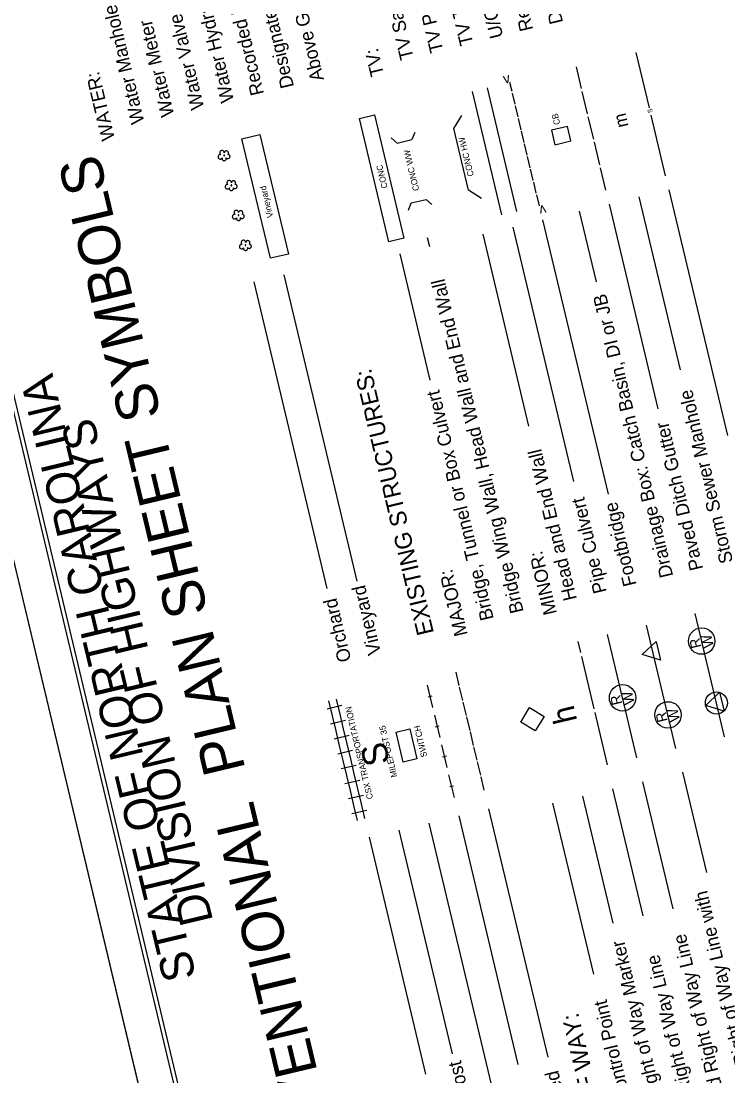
# Model space of a CAD drawing. Extents: x 1734738 to 1742883, y 698103 to 703125.
# Drawn here: x 1737661 to 1738581, y 700083 to 701455 of the extents above; entities that cross this region are included whole.
import ezdxf

# ---------------------------------------------------------------- set-up
doc = ezdxf.new("R2010")
doc.units = 0
for name, color, linetype in [('Exist Map Preparation Border Sheet 1 CELL', 7, 'Continuous'), ('Exist Road Primary Interstate Shield CELL', 7, 'Continuous'), ('Exist Road Primary US Structure Standard Bridge Number Label', 7, 'Continuous'), ('Exist Road Secondary Structure Pipe Number Label', 7, 'Continuous'), ('Exist Road Secondary Type 41 SR Number Label', 7, 'Continuous'), ('Level 57', 7, 'Continuous')]:
    doc.layers.add(name, color=color, linetype=linetype)

msp = doc.modelspace()

# ---------------------------------------------------------------- linework, layer by layer
at = {"layer": 'Exist Road Primary Interstate Shield CELL'}
for p, q in [((1738478.8, 701342.3), (1738461.7, 701414.3)), ((1738390.6, 701367.5), (1738383.9, 701395.7)), ((1738287, 701203), (1738248.8, 701363.5)), ((1738306.5, 701207.6), (1738268.2, 701368.1)), ((1738300.2, 701363.4), (1738297.4, 701375.1)), ((1738398.5, 701334.4), (1738391.5, 701363.6)), ((1738304.2, 701346.9), (1738300.7, 701361.5)), ((1738308.1, 701330.4), (1738304.6, 701344.9)), ((1738224.3, 701315.3), (1738234.8, 701332.3)), ((1738312, 701313.8), (1738308.6, 701328.4)), ((1738406.4, 701301.3), (1738399.4, 701330.5)), ((1738499.9, 701253.7), (1738481.2, 701332.6)), ((1738173.7, 701310.3), (1738170, 701301)), ((1738243.4, 701235), (1738224.3, 701315.3)), ((1738316, 701297.3), (1738312.5, 701311.9)), ((1738143.1, 701303.1), (1738150.5, 701296.4)), ((1738150.5, 701296.4), (1738170, 701301)), ((1738319.9, 701280.7), (1738316.4, 701295.3)), ((1738414.2, 701268.3), (1738407.3, 701297.5)), ((1738323.9, 701264.2), (1738320.4, 701278.8)), ((1738327.8, 701247.7), (1738324.3, 701262.3)), ((1738422.1, 701235.2), (1738415.2, 701264.4)), ((1738331.7, 701231.1), (1738328.3, 701245.7)), ((1738260.5, 701224.5), (1738243.4, 701235)), ((1738335.7, 701214.6), (1738332.2, 701229.2)), ((1738465.3, 701226.4), (1738519, 701001.3)), ((1738504.3, 701235.7), (1738580.4, 700916.2)), ((1738165.4, 701209.3), (1738169.1, 701218.6)), ((1738169.1, 701218.6), (1738188.5, 701223.2)), ((1738196, 701216.6), (1738188.5, 701223.2)), ((1738426.4, 701217.1), (1738489.9, 700950.7)), ((1738387.5, 701207.8), (1738409.4, 701116)), ((1738301.1, 701187.2), (1738380, 700856.1)), ((1738340, 701196.5), (1738425.1, 700839.6)), ((1738193, 701161.5), (1738190.2, 701173.1)), ((1738262.2, 701178), (1738321.7, 700928.3)), ((1738154.1, 701152.2), (1738193.2, 700987.9)), ((1737964.4, 701115.9), (1738059.4, 700717.1)), ((1738003.3, 701125.1), (1738098.3, 700726.4)), ((1738576.6, 700524), (1738538.4, 700684.5)), ((1738513.4, 700508.9), (1738475.1, 700669.5)), ((1738462.6, 700496.8), (1738424.3, 700657.3)), ((1738389.8, 700633.7), (1738386.3, 700648.3)), ((1738407.2, 700560.7), (1738390.9, 700628.8)), ((1738483.5, 700634.3), (1738483.5, 700634.3)), ((1738231.5, 700590.8), (1738227.4, 700608.3)), ((1738197.3, 700562.1), (1738190.3, 700591.3)), ((1738236.2, 700571.4), (1738232, 700588.9)), ((1738066.6, 700551.5), (1738062, 700571)), ((1738076.4, 700553.8), (1738071.7, 700573.3)), ((1738191.4, 700576.1), (1738196.2, 700577.3)), ((1738240.8, 700551.9), (1738236.6, 700569.4)), ((1738566.1, 700568.2), (1738566.1, 700568.2)), ((1738078.9, 700564.7), (1738059.5, 700560.1)), ((1738081, 700534.4), (1738076.4, 700553.8)), ((1738424.5, 700487.8), (1738408.3, 700555.9)), ((1738083.5, 700545.3), (1738064.1, 700540.6)), ((1738071.3, 700532.1), (1738066.6, 700551.5)), ((1738206.5, 700523.2), (1738199.6, 700552.4)), ((1738245.5, 700532.5), (1738241.3, 700550)), ((1738088.2, 700525.8), (1738068.7, 700521.2)), ((1738075.9, 700512.6), (1738071.3, 700532.1)), ((1738085.6, 700514.9), (1738081, 700534.4)), ((1738200.6, 700537.2), (1738205.5, 700538.4)), ((1738250.1, 700513), (1738245.9, 700530.5)), ((1738080.5, 700493.2), (1738075.9, 700512.6)), ((1738090.3, 700495.5), (1738085.6, 700514.9)), ((1738215.8, 700484.3), (1738208.9, 700513.5)), ((1738092.8, 700506.4), (1738073.4, 700501.7)), ((1738209.9, 700498.3), (1738214.8, 700499.4)), ((1738254.7, 700493.6), (1738250.6, 700511.1)), ((1738097.5, 700486.9), (1738078, 700482.3)), ((1738085.2, 700473.7), (1738080.5, 700493.2)), ((1738094.9, 700476), (1738090.3, 700495.5)), ((1738259.4, 700474.1), (1738255.2, 700491.6)), ((1738089.8, 700454.2), (1738085.2, 700473.7)), ((1738099.5, 700456.6), (1738094.9, 700476)), ((1738225.1, 700445.4), (1738218.1, 700474.6)), ((1738264, 700454.6), (1738259.8, 700472.2)), ((1738522, 700478), (1738553.1, 700347.5)), ((1738102.1, 700467.5), (1738082.6, 700462.8)), ((1738219.2, 700459.4), (1738224, 700460.5)), ((1738469.8, 700465.6), (1738509.2, 700300.3)), ((1738106.7, 700448), (1738087.3, 700443.4)), ((1738094.5, 700434.8), (1738089.8, 700454.2)), ((1738104.2, 700437.1), (1738099.5, 700456.6)), ((1738391.9, 700447), (1738431.3, 700281.8)), ((1738430.9, 700456.3), (1738470.2, 700291.1)), ((1738099.1, 700415.3), (1738094.5, 700434.8)), ((1738108.8, 700417.7), (1738104.2, 700437.1)), ((1738269.7, 700430.5), (1738346.8, 700107.3)), ((1738269.7, 700430.5), (1738346.8, 700107.3)), ((1738353, 700437.8), (1738406, 700215.6)), ((1738111.4, 700428.5), (1738091.9, 700423.9)), ((1738230.8, 700421.3), (1738307.9, 700098)), ((1738153, 700402.7), (1738222.4, 700111.8)), ((1738191.9, 700412), (1738291.6, 699993.9)), ((1738114.1, 700393.4), (1738187.6, 700085.2))]:
    msp.add_line(p, q, dxfattribs=at)
for points in [[(1737411.4, 701976.4), (1738106.9, 699058.2), (1740147.7, 699544.6), (1739452.2, 702462.8)], [(1738376.7, 701299.3), (1738372.2, 701318), (1738351.5, 701313), (1738356, 701294.3)], [(1738493.4, 700623.8), (1738469.5, 700631), (1738487.6, 700648.2)], [(1738576, 700557.7), (1738552.1, 700564.8), (1738570.2, 700582)], [(1738158.7, 700491.2), (1738149.4, 700530.1), (1738167.2, 700534.4), (1738176.4, 700495.5)]]:
    msp.add_lwpolyline(points, close=True, dxfattribs=at)
for points in [[(1738140, 701168), (1738101.8, 701328.5), (1738121.2, 701333.1), (1738159.5, 701172.6), (1738140, 701168)], [(1737985.9, 701146.5), (1737948.8, 701302.1), (1737972.1, 701307.7), (1738009.2, 701152), (1737985.9, 701146.5)], [(1737921.4, 701281.3), (1737920.7, 701281.4), (1737920.1, 701281.4), (1737919.5, 701281.1), (1737919, 701280.9), (1737918.6, 701280.5), (1737918.2, 701280.1), (1737917.9, 701279.5), (1737917.7, 701279), (1737917.7, 701278.2), (1737917.8, 701277.7), (1737918, 701277.2), (1737918.4, 701276.6), (1737918.8, 701276.2), (1737919.3, 701275.8), (1737919.9, 701275.7), (1737920.5, 701275.6), (1737921.1, 701275.6), (1737921.6, 701275.8), (1737922.2, 701276), (1737922.6, 701276.4), (1737923.1, 701277), (1737922.9, 701276.4), (1737923, 701275.8), (1737923.1, 701275.2), (1737923.4, 701274.8), (1737923.7, 701274.3), (1737924.2, 701273.9), (1737924.7, 701273.6), (1737925.3, 701273.5), (1737925.8, 701273.5), (1737926.5, 701273.6), (1737927, 701273.8), (1737927.4, 701274.1), (1737927.8, 701274.6), (1737928.1, 701275), (1737928.3, 701275.5), (1737928.4, 701276.2), (1737928.4, 701276.7), (1737928.3, 701277.3), (1737928.6, 701276.8), (1737929.1, 701276.4), (1737929.6, 701276.2), (1737930.2, 701276.2), (1737930.8, 701276.1), (1737931.3, 701276.2), (1737931.9, 701276.5), (1737932.3, 701276.9), (1737932.7, 701277.3), (1737933, 701277.8), (1737933.2, 701278.3), (1737933.3, 701278.9), (1737933.1, 701279.4), (1737933, 701280), (1737932.8, 701280.5), (1737932.3, 701280.9), (1737931.8, 701281.3), (1737930.9, 701281.6)], [(1737930.9, 701281.6), (1737931.3, 701282.9), (1737931.3, 701283.5), (1737931.3, 701284.1), (1737931, 701284.7), (1737930.7, 701285.1), (1737930.3, 701285.6), (1737929.8, 701286), (1737929.3, 701286.1), (1737928.7, 701286.2), (1737928.1, 701286.3), (1737927.5, 701286), (1737927, 701285.8), (1737926.5, 701285.3), (1737926.2, 701284.9), (1737926, 701284.3), (1737925.8, 701283.7), (1737925.8, 701284.3), (1737925.6, 701285), (1737925.3, 701285.4), (1737924.9, 701285.9), (1737924.5, 701286.3), (1737923.9, 701286.6), (1737923.2, 701286.8), (1737922.6, 701286.7), (1737922, 701286.7), (1737921.5, 701286.4), (1737920.9, 701286.1), (1737920.5, 701285.6), (1737920.2, 701285), (1737920, 701284.4), (1737919.9, 701283.8), (1737920, 701283.2), (1737920.1, 701282.6), (1737920.5, 701282.1), (1737920.9, 701281.7), (1737921.4, 701281.3)], [(1737925.2, 701280.4), (1737925.2, 701280.1), (1737925.4, 701280), (1737925.5, 701279.8), (1737925.8, 701279.9), (1737926, 701279.9), (1737926.2, 701280.2), (1737926.1, 701280.4), (1737926, 701280.6), (1737925.8, 701280.8), (1737925.5, 701280.8), (1737925.3, 701280.7), (1737925.2, 701280.4)], [(1737930.6, 701242.4), (1737930, 701242.5), (1737929.4, 701242.5), (1737928.8, 701242.2), (1737928.3, 701242), (1737927.8, 701241.6), (1737927.4, 701241.2), (1737927.2, 701240.6), (1737927, 701240.1), (1737926.9, 701239.3), (1737927.1, 701238.8), (1737927.3, 701238.3), (1737927.6, 701237.7), (1737928, 701237.3), (1737928.5, 701236.9), (1737929.2, 701236.8), (1737929.7, 701236.7), (1737930.3, 701236.7), (1737930.9, 701236.9), (1737931.5, 701237.1), (1737931.9, 701237.5), (1737932.4, 701238.1), (1737932.2, 701237.5), (1737932.3, 701236.9), (1737932.4, 701236.3), (1737932.7, 701235.9), (1737933, 701235.4), (1737933.5, 701235), (1737934, 701234.7), (1737934.6, 701234.6), (1737935.1, 701234.6), (1737935.8, 701234.6), (1737936.2, 701234.9), (1737936.7, 701235.2), (1737937.1, 701235.7), (1737937.4, 701236.1), (1737937.6, 701236.6), (1737937.7, 701237.3), (1737937.7, 701237.8), (1737937.6, 701238.4), (1737937.9, 701237.9), (1737938.4, 701237.5), (1737938.8, 701237.3), (1737939.5, 701237.3), (1737940.1, 701237.2), (1737940.6, 701237.3), (1737941.1, 701237.6), (1737941.6, 701238), (1737942, 701238.4), (1737942.3, 701238.9), (1737942.4, 701239.4), (1737942.5, 701240), (1737942.4, 701240.5), (1737942.2, 701241.1), (1737942, 701241.6), (1737941.5, 701242), (1737941.1, 701242.4), (1737940.1, 701242.7)], [(1737940.1, 701242.7), (1737940.5, 701244), (1737940.6, 701244.6), (1737940.5, 701245.2), (1737940.3, 701245.8), (1737940, 701246.2), (1737939.6, 701246.7), (1737939.1, 701247), (1737938.5, 701247.2), (1737938, 701247.3), (1737937.4, 701247.4), (1737936.8, 701247.1), (1737936.2, 701246.9), (1737935.8, 701246.4), (1737935.4, 701246), (1737935.3, 701245.4), (1737935.1, 701244.8), (1737935.1, 701245.4), (1737934.9, 701246.1), (1737934.6, 701246.5), (1737934.2, 701247), (1737933.8, 701247.4), (1737933.2, 701247.7), (1737932.5, 701247.8), (1737931.9, 701247.8), (1737931.3, 701247.8), (1737930.7, 701247.5), (1737930.2, 701247.2), (1737929.8, 701246.7), (1737929.4, 701246.1), (1737929.3, 701245.5), (1737929.2, 701244.9), (1737929.3, 701244.3), (1737929.4, 701243.7), (1737929.7, 701243.2), (1737930.1, 701242.8), (1737930.6, 701242.4)], [(1737934.4, 701241.5), (1737934.5, 701241.2), (1737934.7, 701241.1), (1737934.8, 701240.9), (1737935.1, 701241), (1737935.3, 701241), (1737935.4, 701241.2), (1737935.4, 701241.5), (1737935.3, 701241.7), (1737935.1, 701241.9), (1737934.8, 701241.9), (1737934.6, 701241.8), (1737934.4, 701241.5)], [(1737939.9, 701203.5), (1737939.3, 701203.6), (1737938.7, 701203.6), (1737938.1, 701203.3), (1737937.5, 701203.1), (1737937.1, 701202.7), (1737936.7, 701202.3), (1737936.4, 701201.7), (1737936.3, 701201.1), (1737936.2, 701200.4), (1737936.3, 701199.9), (1737936.6, 701199.4), (1737936.9, 701198.8), (1737937.3, 701198.4), (1737937.8, 701198), (1737938.5, 701197.9), (1737939, 701197.8), (1737939.6, 701197.8), (1737940.2, 701198), (1737940.8, 701198.2), (1737941.2, 701198.6), (1737941.7, 701199.1), (1737941.5, 701198.6), (1737941.5, 701198), (1737941.7, 701197.4), (1737942, 701197), (1737942.3, 701196.5), (1737942.8, 701196.1), (1737943.3, 701195.8), (1737943.8, 701195.6), (1737944.3, 701195.7), (1737945, 701195.7), (1737945.5, 701195.9), (1737946, 701196.3), (1737946.3, 701196.8), (1737946.7, 701197.1), (1737946.8, 701197.7), (1737947, 701198.4), (1737947, 701198.9), (1737946.8, 701199.4), (1737947.1, 701199), (1737947.7, 701198.6), (1737948.1, 701198.4), (1737948.7, 701198.4), (1737949.4, 701198.3), (1737949.9, 701198.4), (1737950.4, 701198.7), (1737950.8, 701199.1), (1737951.2, 701199.5), (1737951.5, 701200), (1737951.7, 701200.5), (1737951.8, 701201), (1737951.7, 701201.6), (1737951.5, 701202.2), (1737951.3, 701202.7), (1737950.8, 701203.1), (1737950.4, 701203.5), (1737949.4, 701203.8)], [(1737949.4, 701203.8), (1737949.8, 701205.1), (1737949.9, 701205.7), (1737949.8, 701206.3), (1737949.6, 701206.9), (1737949.3, 701207.3), (1737948.9, 701207.7), (1737948.4, 701208.1), (1737947.8, 701208.3), (1737947.3, 701208.4), (1737946.6, 701208.4), (1737946.1, 701208.2), (1737945.5, 701208), (1737945, 701207.4), (1737944.7, 701207.1), (1737944.5, 701206.5), (1737944.4, 701205.9), (1737944.3, 701206.5), (1737944.2, 701207.1), (1737943.9, 701207.6), (1737943.4, 701208.1), (1737943, 701208.5), (1737942.5, 701208.8), (1737941.8, 701208.9), (1737941.2, 701208.9), (1737940.6, 701208.9), (1737940, 701208.6), (1737939.5, 701208.3), (1737939.1, 701207.8), (1737938.7, 701207.2), (1737938.5, 701206.6), (1737938.5, 701206), (1737938.5, 701205.4), (1737938.7, 701204.8), (1737939, 701204.3), (1737939.4, 701203.8), (1737939.9, 701203.5)], [(1737943.7, 701202.6), (1737943.8, 701202.3), (1737943.9, 701202.1), (1737944.1, 701202), (1737944.4, 701202), (1737944.6, 701202.1), (1737944.7, 701202.3), (1737944.6, 701202.6), (1737944.6, 701202.8), (1737944.4, 701203), (1737944, 701203), (1737943.9, 701202.9), (1737943.7, 701202.6)], [(1737949.2, 701164.5), (1737948.5, 701164.7), (1737947.9, 701164.7), (1737947.4, 701164.4), (1737946.8, 701164.2), (1737946.4, 701163.8), (1737946, 701163.4), (1737945.7, 701162.8), (1737945.5, 701162.2), (1737945.5, 701161.5), (1737945.6, 701161), (1737945.8, 701160.5), (1737946.2, 701159.9), (1737946.6, 701159.5), (1737947.1, 701159.1), (1737947.7, 701159), (1737948.3, 701158.9), (1737948.9, 701158.9), (1737949.5, 701159.1), (1737950, 701159.3), (1737950.4, 701159.7), (1737950.9, 701160.2), (1737950.8, 701159.7), (1737950.8, 701159.1), (1737950.9, 701158.5), (1737951.3, 701158), (1737951.6, 701157.6), (1737952.1, 701157.2), (1737952.6, 701156.9), (1737953.1, 701156.7), (1737953.6, 701156.8), (1737954.3, 701156.8), (1737954.8, 701157), (1737955.2, 701157.3), (1737955.6, 701157.9), (1737955.9, 701158.2), (1737956.1, 701158.8), (1737956.3, 701159.4), (1737956.2, 701160), (1737956.1, 701160.5), (1737956.4, 701160.1), (1737956.9, 701159.7), (1737957.4, 701159.5), (1737958, 701159.4), (1737958.6, 701159.4), (1737959.1, 701159.5), (1737959.7, 701159.7), (1737960.1, 701160.2), (1737960.5, 701160.6), (1737960.8, 701161), (1737961, 701161.6), (1737961.1, 701162.1), (1737960.9, 701162.7), (1737960.8, 701163.3), (1737960.6, 701163.8), (1737960.1, 701164.2), (1737959.7, 701164.6), (1737958.7, 701164.9)], [(1737958.7, 701164.9), (1737959.1, 701166.2), (1737959.1, 701166.8), (1737959.1, 701167.4), (1737958.9, 701168), (1737958.5, 701168.4), (1737958.1, 701168.8), (1737957.6, 701169.2), (1737957.1, 701169.4), (1737956.5, 701169.5), (1737955.9, 701169.5), (1737955.4, 701169.3), (1737954.8, 701169.1), (1737954.3, 701168.5), (1737954, 701168.2), (1737953.8, 701167.6), (1737953.7, 701166.9), (1737953.6, 701167.6), (1737953.5, 701168.2), (1737953.1, 701168.7), (1737952.7, 701169.2), (1737952.3, 701169.6), (1737951.7, 701169.9), (1737951.1, 701170), (1737950.5, 701170), (1737949.9, 701169.9), (1737949.3, 701169.7), (1737948.8, 701169.4), (1737948.4, 701168.9), (1737948, 701168.3), (1737947.8, 701167.7), (1737947.8, 701167.1), (1737947.8, 701166.5), (1737947.9, 701165.9), (1737948.3, 701165.4), (1737948.7, 701164.9), (1737949.2, 701164.5)], [(1737953, 701163.7), (1737953.1, 701163.4), (1737953.2, 701163.2), (1737953.3, 701163.1), (1737953.6, 701163.1), (1737953.8, 701163.2), (1737954, 701163.4), (1737953.9, 701163.7), (1737953.9, 701163.9), (1737953.6, 701164.1), (1737953.3, 701164.1), (1737953.1, 701163.9), (1737953, 701163.7)]]:
    msp.add_lwpolyline(points, dxfattribs=at)
for centre, radius in [((1738546.9, 700648.7), 17.2), ((1738444, 700574.9), 17.2), ((1738566.1, 700568.2), 14.4), ((1738503, 700552.6), 17.2)]:
    msp.add_circle(centre, radius, dxfattribs=at)
at = {"layer": 'Exist Road Primary US Structure Standard Bridge Number Label'}
msp.add_line((1737354.8, 701997.9), (1738135.7, 698721.7), dxfattribs=at)
at = {"layer": 'Exist Road Secondary Structure Pipe Number Label'}
msp.add_lwpolyline([(1740226.1, 699246.6), (1739453.3, 702488.8), (1737400.6, 701999.6), (1738173.4, 698757.4)], close=True, dxfattribs=at)
at = {"layer": 'Exist Road Secondary Type 41 SR Number Label'}
msp.add_lwpolyline([(1740275.8, 699231.7), (1739494.9, 702508), (1737354.8, 701997.9), (1738135.7, 698721.7)], close=True, dxfattribs=at)
at = {"layer": 'Level 57'}
msp.add_lwpolyline([(1738330.2, 700531.7), (1738311.4, 700543.3), (1738323, 700562.2), (1738341.8, 700550.6)], close=True, dxfattribs=at)

# ---------------------------------------------------------------- texts
at = {"layer": 'Exist Map Preparation Border Sheet 1 CELL'}
msp.add_text('2. CLEARING ON THIS PROJECT SHALL BE PERFORMED TO THE LIMITS ESTABLISHED BY METHOD III.', height=17.5, rotation=103.4059, dxfattribs=at).set_placement((1737758.6, 699133.5))
at = {"layer": 'Exist Road Primary Interstate Shield CELL'}
for s, height, rotation, p in [('Designated U/G TV Cable (S.U.E.*)', 17.5, 103.4059, (1738366.7, 701453.4)), ('Designated U/G Water Line (S.U.E.*)', 17.5, 103.4059, (1738016.6, 701369.9)), ('U/G TV Cable Hand Hole', 17.5, 103.4059, (1738288.9, 701434.8)), ('Recorded U/G TV Cable', 17.5, 103.4059, (1738327.8, 701444.1)), ('Above Ground Water Line', 17.5, 103.4059, (1738055.5, 701379.2)), ('Recorded U/G Water Line', 17.5, 103.4059, (1737977.6, 701360.6)), ('TV Satellite Dish', 17.5, 103.4059, (1738172.2, 701407)), ('TV Pedestal', 17.5, 103.4059, (1738211.1, 701416.3)), ('TV Tower', 17.5, 103.4059, (1738250, 701425.5)), ('Water Hydrant', 17.5, 103.4059, (1737938.7, 701351.3)), ('Water Manhole', 17.5, 103.4059, (1737822, 701323.5)), ('Water Valve', 17.5, 103.4059, (1737899.8, 701342.1)), ('Water Meter', 17.5, 103.4059, (1737860.9, 701332.8)), ('TV:', 17.5, 103.4059, (1738133.8, 701385.4)), ('WATER:', 17.5, 103.4059, (1737783.6, 701301.9)), ('v', 13.2, 13.6468, (1738290.2, 701373.3)), ('CB', 8, 103.4059, (1738362.9, 701321.2)), ('m', 16.5, 103.4059, (1738451.8, 701318.6)), ('S', 6, 103.4059, (1738483.3, 701336.4)), ('CONC HW', 8, 103.4059, (1738250.5, 701254)), ('CONC WW', 8, 103.4059, (1738179.5, 701235.2)), ('CONVENTIONAL  PLAN SHEET SYMBOLS', 54.401, 103.4059, (1738096, 699884.1)), ('CONC', 8, 103.4059, (1738138.4, 701238.4)), ('Vineyard', 8, 103.4059, (1737989.5, 701200.4)), ('v', 13.2, 193.1651, (1738343, 701216.3)), ('Bridge Wing Wall, Head Wall and End Wall', 17.5, 103.4059, (1738315.4, 700687)), ('Drainage Box: Catch Basin, DI or JB', 17.5, 103.4059, (1738509.9, 700733.4)), ('STATE OF NORTH CAROLINA', 42.838, 103.4059, (1737889.4, 700211.8)), ('EXISTING STRUCTURES:', 22, 103.4059, (1738198.7, 700659.2)), ('Bridge, Tunnel or Box Culvert', 17.5, 103.4059, (1738276.5, 700677.7)), ('Storm Sewer Manhole', 17.5, 103.4059, (1738587.8, 700751.9)), ('DIVISION OF HIGHWAYS', 42.838, 103.4059, (1737911.5, 700284.6)), ('Paved Ditch Gutter', 17.5, 103.4059, (1738548.9, 700742.7)), ('Head and End Wall', 17.5, 103.4059, (1738384.6, 700703.5)), ('Pipe Culvert', 17.5, 103.4059, (1738423.5, 700712.8)), ('Footbridge', 17.5, 103.4059, (1738462.4, 700722.1)), ('MINOR:', 17.5, 103.4059, (1738358.7, 700684.9)), ('MAJOR:', 17.5, 103.4059, (1738242.6, 700657.2)), ('Vineyard', 17.5, 103.4059, (1738130, 700632.8)), ('Orchard', 17.5, 103.4059, (1738091.1, 700623.5)), ('R', 13.5, 103.4059, (1738546.7, 700641)), ('W', 13.5, 103.4059, (1738562.8, 700641.7)), ('W', 13.5, 103.4059, (1738459.9, 700567.9)), ('R', 13.5, 103.4059, (1738443.7, 700567.2)), ('CSX TRANSPORTATION', 8, 103.4059, (1738119.5, 700444)), ('h', 30, 103.4059, (1738385.1, 700545.2)), ('R', 13.5, 103.4059, (1738502.8, 700544.9)), ('W', 13.5, 103.4059, (1738518.9, 700545.6)), ('MILEPOST 35', 8, 103.4059, (1738150.9, 700472.4)), ('SWITCH', 8, 103.4059, (1738189.9, 700498.6)), ('S', 33, 103.4059, (1738141.5, 700490.8)), ('Proposed Right of Way Line with', 17.5, 103.4059, (1738632.4, 699995)), ('Proposed Right of Way Line', 17.5, 103.4059, (1738593.5, 699985.7)), ('Existing Right of Way Marker', 17.5, 103.4059, (1738515.7, 699967.2)), ('Existing Right of Way Line', 17.5, 103.4059, (1738554.6, 699976.4)), ('Baseline Control Point', 17.5, 103.4059, (1738476.8, 699957.9)), ('RIGHT OF WAY:', 22, 103.4059, (1738437.9, 699948.6)), ('RR Signal Milepost', 17.5, 103.4059, (1738279.7, 699910.3)), ('RR Dismantled', 17.5, 103.4059, (1738396.4, 699938.2))]:
    msp.add_text(s, height=height, rotation=rotation, dxfattribs=at).set_placement(p)

doc.saveas('drawing.dxf')
